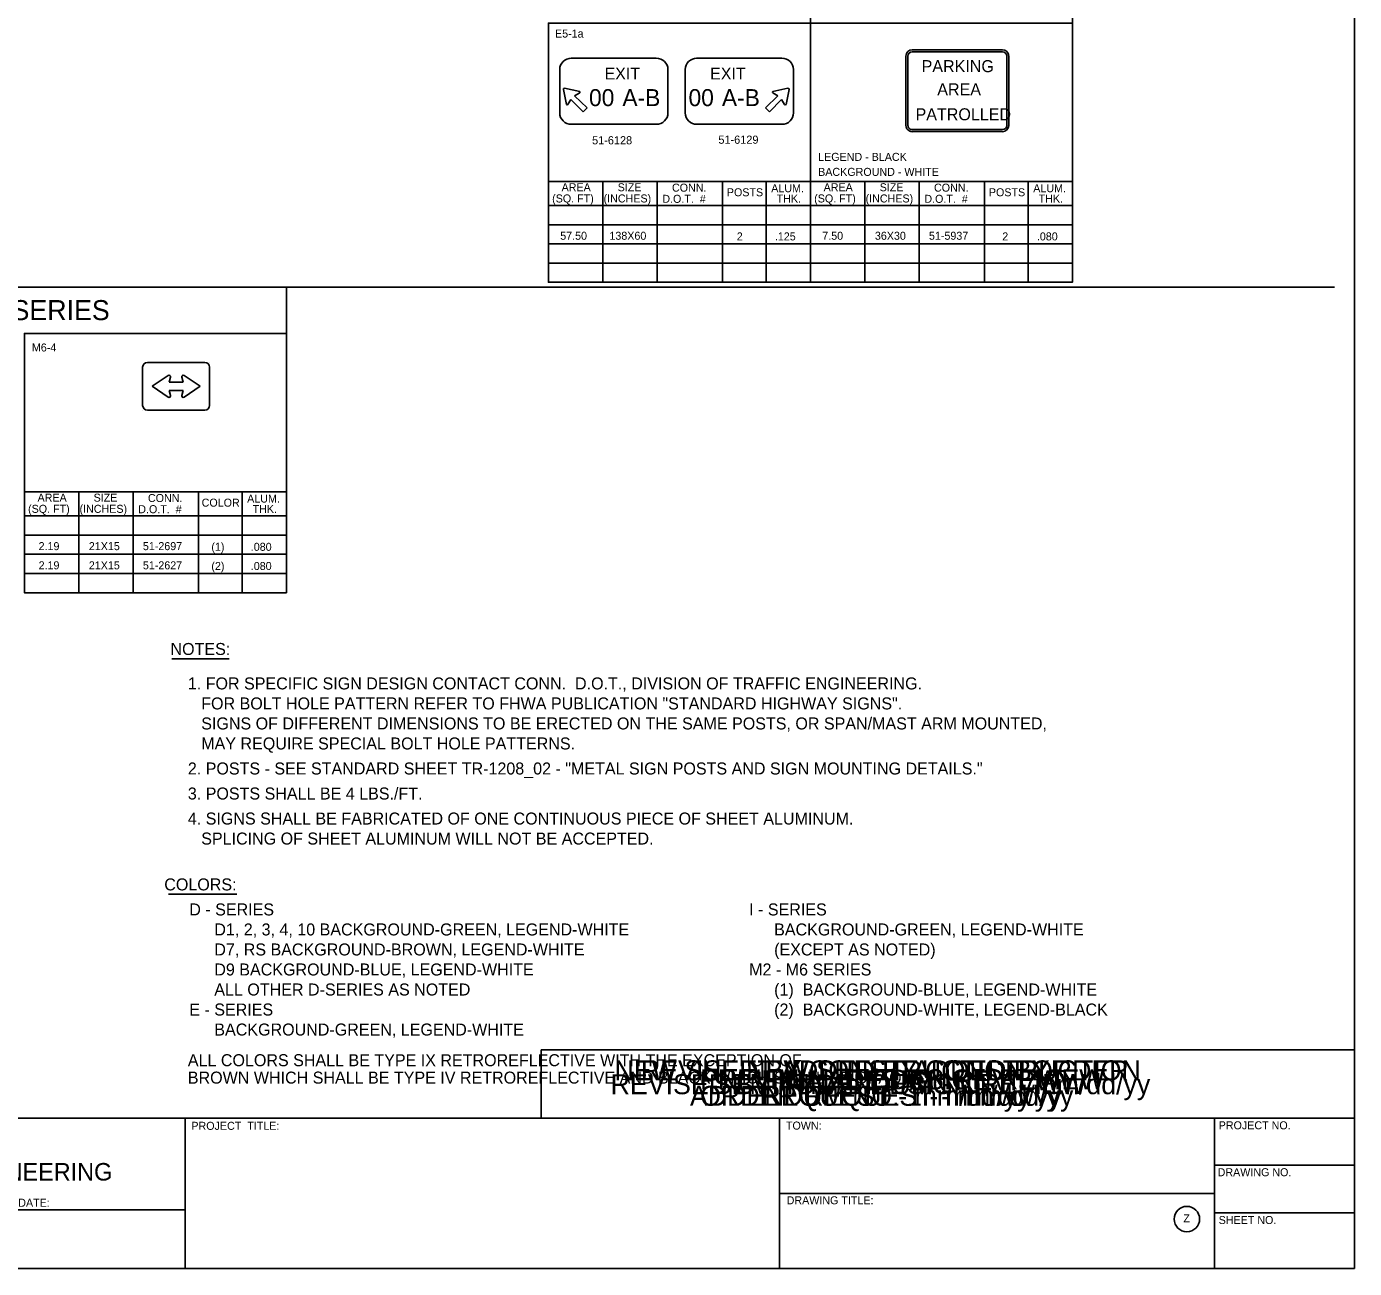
# Model space of a CAD drawing. Extents: x 0 to 2011, y -22 to 1183.
# Drawn here: x 739 to 1270, y -1 to 495 of the extents above; entities that cross this region are included whole.
import ezdxf

# ---------------------------------------------------------------- set-up
doc = ezdxf.new("R2010")
doc.units = 0
for name, color, linetype in [('CT_Bdr_Txt_Titleblock', 7, 'Continuous'), ('CT_Border_Perimeter_Shape', 7, 'Continuous'), ('CT_Construction', 7, 'Continuous'), ('CT_Note_Final_Design_Review', 7, 'Continuous'), ('CT_Note_New_Sheet_by_Addendum', 7, 'Continuous'), ('CT_Note_New_Sheet_by_Const_Order', 7, 'Continuous'), ('CT_Note_Preliminary_Design_Review', 7, 'Continuous'), ('CT_Note_Revised_Sheet_by_Addendum', 7, 'Continuous'), ('CT_Note_Revised_Sheet_by_Const_Order', 7, 'Continuous'), ('CT_Note_Semi_Final_Design_Review', 7, 'Continuous'), ('CT_Signature_Field_CTDOT', 7, 'Continuous'), ('CT_Title_Block_Linework', 7, 'Continuous'), ('CT_Title_Block_Text', 7, 'Continuous'), ('Default', 7, 'Continuous'), ('Level 1', 7, 'Continuous'), ('Level 2', 7, 'Continuous'), ('Level 5', 7, 'Continuous')]:
    doc.layers.add(name, color=color, linetype=linetype)

msp = doc.modelspace()

# ---------------------------------------------------------------- linework, layer by layer
at = {"layer": 'CT_Border_Perimeter_Shape'}
msp.add_lwpolyline([(0, -0.97), (1270, -0.97), (1270, 829.03), (0, 829.03)], close=True, dxfattribs=at)
at = {"layer": 'CT_Construction'}
msp.add_lwpolyline([(0, 829.03), (1270, 829.03), (1270, 59.03), (0, 59.03)], close=True, dxfattribs=at)
at = {"layer": 'CT_Note_Final_Design_Review'}
msp.add_lwpolyline([(944.83, 86.47), (1270, 86.47), (1270, 59.03), (944.83, 59.03)], close=True, dxfattribs=at)
at = {"layer": 'CT_Note_New_Sheet_by_Addendum'}
msp.add_lwpolyline([(944.83, 86.47), (1270, 86.47), (1270, 59.03), (944.83, 59.03)], close=True, dxfattribs=at)
msp.add_lwpolyline([(944.83, 86.47), (1270, 86.47), (1270, 59.03), (944.83, 59.03)], close=True, dxfattribs=at)
at = {"layer": 'CT_Note_New_Sheet_by_Const_Order'}
msp.add_lwpolyline([(944.83, 86.47), (1270, 86.47), (1270, 59.03), (944.83, 59.03)], close=True, dxfattribs=at)
msp.add_lwpolyline([(944.83, 86.47), (1270, 86.47), (1270, 59.03), (944.83, 59.03)], close=True, dxfattribs=at)
at = {"layer": 'CT_Note_Preliminary_Design_Review'}
msp.add_lwpolyline([(944.83, 86.47), (1270, 86.47), (1270, 59.03), (944.83, 59.03)], close=True, dxfattribs=at)
at = {"layer": 'CT_Note_Revised_Sheet_by_Addendum'}
msp.add_lwpolyline([(944.83, 86.47), (1270, 86.47), (1270, 59.03), (944.83, 59.03)], close=True, dxfattribs=at)
msp.add_lwpolyline([(944.83, 86.47), (1270, 86.47), (1270, 59.03), (944.83, 59.03)], close=True, dxfattribs=at)
at = {"layer": 'CT_Note_Revised_Sheet_by_Const_Order'}
msp.add_lwpolyline([(944.83, 86.47), (1270, 86.47), (1270, 59.03), (944.83, 59.03)], close=True, dxfattribs=at)
msp.add_lwpolyline([(944.83, 86.47), (1270, 86.47), (1270, 59.03), (944.83, 59.03)], close=True, dxfattribs=at)
at = {"layer": 'CT_Note_Semi_Final_Design_Review'}
msp.add_lwpolyline([(944.83, 86.47), (1270, 86.47), (1270, 59.03), (944.83, 59.03)], close=True, dxfattribs=at)
msp.add_lwpolyline([(944.83, 86.47), (1270, 86.47), (1270, 59.03), (944.83, 59.03)], close=True, dxfattribs=at)
at = {"layer": 'CT_Signature_Field_CTDOT'}
msp.add_line((651.86, 22.46), (802.52, 22.46), dxfattribs=at)
at = {"layer": 'CT_Title_Block_Linework'}
for p, q in [((1270, 59.03), (0, 59.03)), ((802.52, 59.03), (802.52, -0.97)), ((1040.16, 59.03), (1040.16, -0.97)), ((1214.02, 59.03), (1214.02, -0.97)), ((1214.02, 40.28), (1270, 40.28)), ((1040.16, 29.03), (1214.02, 29.03)), ((1214.02, 21.28), (1270, 21.28))]:
    msp.add_line(p, q, dxfattribs=at)
msp.add_circle((1203.02, 18.75), 5.08, dxfattribs=at)
at = {"layer": 'Default'}
msp.add_line((1262.03, 391.26), (5.05, 391.26), dxfattribs=at)
at = {"layer": 'Level 1'}
for p, q in [((1090.71, 455.87), (1090.71, 483.65)), ((1091.52, 455.87), (1091.52, 483.65)), ((1093.18, 486.11), (1129.32, 486.11)), ((1093.18, 485.31), (1129.32, 485.31)), ((1130.98, 483.65), (1130.98, 455.87)), ((1131.79, 483.65), (1131.79, 455.87)), ((952.3, 460.89), (952.3, 478.22)), ((956.86, 482.76), (986.55, 482.76)), ((956.86, 482.76), (990.9, 482.76)), ((995.57, 478.22), (995.57, 460.6)), ((1002.48, 460.89), (1002.48, 478.22)), ((1007.04, 482.76), (1036.73, 482.76)), ((1007.04, 482.76), (1041.09, 482.76)), ((1045.76, 478.22), (1045.76, 460.6)), ((953.76, 470.24), (954.97, 464.2)), ((960.29, 469.52), (954.25, 470.73)), ((958.25, 467.72), (960.29, 468.93)), ((963.21, 462.87), (958.25, 467.72)), ((1034.53, 462.87), (1039.49, 467.72)), ((1037.45, 469.52), (1043.49, 470.73)), ((1039.49, 467.72), (1037.45, 468.93)), ((1043.98, 470.24), (1042.77, 464.2)), ((955.56, 464.2), (956.77, 466.24)), ((956.77, 466.24), (961.62, 461.28)), ((961.62, 461.28), (963.21, 462.87)), ((1036.12, 461.28), (1034.53, 462.87)), ((1040.97, 466.24), (1036.12, 461.28)), ((1042.18, 464.2), (1040.97, 466.24)), ((990.9, 456.36), (956.97, 456.36)), ((1041.09, 456.36), (1007.15, 456.36)), ((1129.32, 454.21), (1093.18, 454.21)), ((1129.32, 453.41), (1093.18, 453.41)), ((810.43, 361.2), (787.48, 361.2)), ((810.43, 361.2), (787.48, 361.2)), ((785.57, 359.29), (785.57, 343.99)), ((785.57, 359.29), (785.57, 343.99)), ((795.73, 355.99), (789.39, 351.64)), ((808.52, 351.64), (802.18, 355.99)), ((812.34, 343.99), (812.34, 359.29)), ((812.34, 343.99), (812.34, 359.29)), ((789.39, 351.64), (789.39, 351.64)), ((789.39, 351.64), (795.73, 347.29)), ((796.11, 353.32), (796.7, 355.28)), ((801.8, 353.32), (796.11, 353.32)), ((801.21, 355.28), (801.8, 353.32)), ((802.18, 347.29), (808.52, 351.64)), ((808.52, 351.64), (808.52, 351.64)), ((808.52, 351.64), (808.52, 351.64)), ((796.7, 348), (796.11, 349.97)), ((796.11, 349.97), (801.8, 349.97)), ((801.8, 349.97), (801.21, 348)), ((787.48, 342.08), (810.43, 342.08)), ((787.48, 342.08), (810.43, 342.08)), ((797.3, 242.69), (820.15, 242.69)), ((795.89, 148.62), (823.17, 148.62))]:
    msp.add_line(p, q, dxfattribs=at)
for centre, radius, start, end in [((1093.18, 483.65), 2.47, 90, 180), ((1093.18, 483.65), 1.66, 90, 180), ((1129.32, 483.65), 2.47, 0.0023, 89.9991), ((1129.32, 483.65), 1.66, 0.0023, 89.9987), ((954.17, 470.32), 0.418, 78.7145, 191.291), ((959.99, 469.23), 0.418, 315, 45), ((1037.75, 469.23), 0.418, 135, 225), ((1043.57, 470.32), 0.418, 348.709, 101.2855), ((955.26, 464.5), 0.418, 225, 315), ((1042.47, 464.5), 0.418, 225, 315), ((1093.18, 455.87), 2.47, 179.998, 270), ((1089.87, 455.87), 0.84, 359.998, 0), ((1093.18, 455.87), 1.66, 179.998, 270), ((1089.87, 455.87), 1.64, 359.998, 0), ((1093.18, 452.57), 1.64, 90, 90.0015), ((1093.18, 452.57), 0.84, 90, 90.0015), ((1129.32, 455.87), 1.66, 270, 360), ((1129.32, 455.87), 2.47, 270, 360), ((787.48, 359.29), 1.91, 90, 180), ((787.48, 359.29), 1.91, 90, 180), ((810.43, 359.29), 1.91, 0, 90), ((810.43, 359.29), 1.91, 0, 90), ((796.09, 355.47), 0.637, 343.3591, 124.4886), ((801.82, 355.47), 0.637, 55.5114, 196.6409), ((796.09, 347.82), 0.637, 235.5114, 16.6409), ((801.82, 347.82), 0.637, 163.3591, 304.4886), ((787.48, 343.99), 1.91, 180, 270), ((787.48, 343.99), 1.91, 180, 270), ((810.43, 343.99), 1.91, 270, 360), ((810.43, 343.99), 1.91, 270, 360)]:
    msp.add_arc(centre, radius, start, end, dxfattribs=at)
for centre, major_axis, ratio, start_param, end_param in [((956.97, 478.22), (-4.67, 0), 0.970874, 4.712389, 6.283185), ((990.9, 478.22), (-4.67, 0), 0.97089, 3.141593, 4.712389), ((1007.15, 478.22), (-4.67, 0), 0.970874, 4.712389, 6.283185), ((1041.09, 478.22), (-4.67, 0), 0.97089, 3.141593, 4.712389), ((956.97, 460.89), (4.67, 0), 0.970874, 3.141593, 4.712389), ((990.9, 460.89), (4.67, 0), 0.970874, 4.712389, 6.283185), ((1007.15, 460.89), (4.67, 0), 0.970874, 3.141593, 4.712389), ((1041.09, 460.89), (4.67, 0), 0.970874, 4.712389, 6.283185)]:
    msp.add_ellipse(centre, major_axis=major_axis, ratio=ratio, start_param=start_param, end_param=end_param, dxfattribs=at)
at = {"layer": 'Level 2'}
for p, q in [((947.79, 433.47), (1052.53, 433.47)), ((969.54, 433.47), (969.54, 393.19)), ((991.29, 433.47), (991.29, 393.19)), ((1017.39, 433.47), (1017.39, 393.19)), ((1034.79, 433.47), (1034.79, 393.19)), ((1052.53, 433.47), (1157.28, 433.47)), ((1074.28, 433.47), (1074.28, 393.19)), ((1096.03, 433.47), (1096.03, 393.19)), ((1122.13, 433.47), (1122.13, 393.19)), ((1139.53, 433.47), (1139.53, 393.19)), ((947.79, 423.88), (1052.53, 423.88)), ((1052.53, 423.88), (1157.28, 423.88)), ((947.79, 416.2), (1052.53, 416.2)), ((1052.53, 416.2), (1157.28, 416.2)), ((947.79, 408.53), (1052.53, 408.53)), ((1052.53, 408.53), (1157.28, 408.53)), ((947.79, 400.86), (1052.53, 400.86)), ((1052.53, 400.86), (1157.28, 400.86)), ((812.34, 361.2), (812.34, 361.2)), ((785.57, 342.08), (785.57, 342.08)), ((738.29, 309.4), (843.04, 309.4)), ((760.04, 309.4), (760.04, 269.13)), ((781.79, 309.4), (781.79, 269.13)), ((807.89, 309.4), (807.89, 269.13)), ((825.29, 309.4), (825.29, 269.13)), ((738.29, 299.81), (843.04, 299.81)), ((738.29, 292.14), (843.04, 292.14)), ((738.29, 284.47), (843.04, 284.47)), ((738.29, 276.8), (843.04, 276.8))]:
    msp.add_line(p, q, dxfattribs=at)
for points in [[(1052.53, 496.81), (947.79, 496.81), (947.79, 393.19), (1052.53, 393.19)], [(1157.28, 496.81), (1052.53, 496.81), (1052.53, 393.19), (1157.28, 393.19)], [(843.04, 372.75), (738.29, 372.75), (738.29, 269.13), (843.04, 269.13)]]:
    msp.add_lwpolyline(points, close=True, dxfattribs=at)
msp.add_lwpolyline([(804.12, 354.65), (804.12, 354.66)], dxfattribs=at)
at = {"layer": 'Level 5'}
for p, q in [((1052.53, 830), (1052.53, 393.19)), ((1157.28, 830), (1157.28, 393.19)), ((843.04, 391.26), (843.04, 269.13))]:
    msp.add_line(p, q, dxfattribs=at)

# ---------------------------------------------------------------- texts
at = {"layer": 'CT_Bdr_Txt_Titleblock'}
msp.add_text('Z', height=3.2, dxfattribs=at).set_placement((1201.62, 17.47))
at = {"layer": 'CT_Note_Final_Design_Review'}
msp.add_text('FINAL DESIGN REVIEW', height=8, dxfattribs=at).set_placement((1032.99, 70.22))
at = {"layer": 'CT_Note_New_Sheet_by_Addendum'}
for s, p in [('NEW SHEET ADDED BY', (1026.89, 74.2)), ('ADDENDUM NO. 1 - mm/dd/yy', (1004.36, 64.04))]:
    msp.add_text(s, height=8, dxfattribs=at).set_placement(p)
at = {"layer": 'CT_Note_New_Sheet_by_Const_Order'}
for s, p in [('NEW SHEET ADDED BY CONSTRUCTION', (974.21, 74.2)), ('ORDER REQUEST - mm/dd/yy', (1008.44, 64.04))]:
    msp.add_text(s, height=8, dxfattribs=at).set_placement(p)
at = {"layer": 'CT_Note_Preliminary_Design_Review'}
msp.add_text('PRELIMINARY DESIGN REVIEW', height=8, rotation=360, dxfattribs=at).set_placement((1008.39, 70.59))
at = {"layer": 'CT_Note_Revised_Sheet_by_Addendum'}
msp.add_text('REVISED BY ADDENDUM NO. 1 - mm/dd/yy', height=8, dxfattribs=at).set_placement((972.63, 68.66))
at = {"layer": 'CT_Note_Revised_Sheet_by_Const_Order'}
for s, p in [('REVISED BY CONSTRUCTION ORDER', (984.74, 74.19)), ('REQUEST - mm/dd/yy', (1032.95, 64.03))]:
    msp.add_text(s, height=8, dxfattribs=at).set_placement(p)
at = {"layer": 'CT_Note_Semi_Final_Design_Review'}
msp.add_text('SEMI FINAL DESIGN REVIEW', height=8, dxfattribs=at).set_placement((1013.84, 68.77))
at = {"layer": 'CT_Signature_Field_CTDOT'}
for s, height, p in [('OFFICE OF ENGINEERING', 7, (655.38, 34.16)), ('DATE:  ', 3.2, (735.85, 23.69))]:
    msp.add_text(s, height=height, rotation=360, dxfattribs=at).set_placement(p)
at = {"layer": 'CT_Title_Block_Text'}
for s, p in [('PROJECT  TITLE:', (805.05, 54.43)), ('TOWN:', (1042.74, 54.53)), ('PROJECT NO.', (1215.74, 54.64)), ('DRAWING NO.', (1215.31, 35.88)), ('DRAWING TITLE:', (1043.02, 24.66)), ('SHEET NO.', (1215.72, 16.78))]:
    msp.add_text(s, height=3.2, rotation=360, dxfattribs=at).set_placement(p)
at = {"layer": 'Level 1'}
for s, height, p in [('51-6128', 3.264, (965.24, 448.33)), ('51-6129', 3.264, (1015.73, 448.57)), ('M6 - SERIES', 8, (708.8, 378.08)), ('NOTES:', 4.8, (796.71, 244.23)), ('1. FOR SPECIFIC SIGN DESIGN CONTACT CONN.  D.O.T., DIVISION OF TRAFFIC ENGINEERING.', 4.8, (803.64, 230.46)), ('   FOR BOLT HOLE PATTERN REFER TO FHWA PUBLICATION "STANDARD HIGHWAY SIGNS".', 4.8, (803.64, 222.46)), ('   SIGNS OF DIFFERENT DIMENSIONS TO BE ERECTED ON THE SAME POSTS, OR SPAN/MAST ARM MOUNTED,', 4.8, (803.64, 214.46)), ('   MAY REQUIRE SPECIAL BOLT HOLE PATTERNS.', 4.8, (803.64, 206.46)), ('2. POSTS - SEE STANDARD SHEET TR-1208_02 - "METAL SIGN POSTS AND SIGN MOUNTING DETAILS."', 4.8, (803.64, 196.46)), ('3. POSTS SHALL BE 4 LBS./FT.', 4.8, (803.64, 186.46)), ('4. SIGNS SHALL BE FABRICATED OF ONE CONTINUOUS PIECE OF SHEET ALUMINUM.', 4.8, (803.64, 176.46)), ('   SPLICING OF SHEET ALUMINUM WILL NOT BE ACCEPTED.', 4.8, (803.64, 168.46)), ('COLORS:', 4.8, (794.22, 150.12)), ('D - SERIES', 4.8, (804.22, 140.12)), ('I - SERIES', 4.8, (1028.02, 140.12)), ('D1, 2, 3, 4, 10 BACKGROUND-GREEN, LEGEND-WHITE', 4.8, (814.22, 132.12)), ('BACKGROUND-GREEN, LEGEND-WHITE', 4.8, (1038.02, 132.12)), ('D7, RS BACKGROUND-BROWN, LEGEND-WHITE', 4.8, (814.22, 124.12)), ('(EXCEPT AS NOTED)', 4.8, (1038.02, 124.12)), ('D9 BACKGROUND-BLUE, LEGEND-WHITE', 4.8, (814.22, 116.12)), ('M2 - M6 SERIES', 4.8, (1028.02, 116.12)), ('ALL OTHER D-SERIES AS NOTED', 4.8, (814.22, 108.12)), ('(1)  BACKGROUND-BLUE, LEGEND-WHITE', 4.8, (1038.02, 108.12)), ('E - SERIES', 4.8, (804.22, 100.12)), ('(2)  BACKGROUND-WHITE, LEGEND-BLACK', 4.8, (1038.02, 100.12)), ('BACKGROUND-GREEN, LEGEND-WHITE', 4.8, (814.22, 92.12)), ('ALL COLORS SHALL BE TYPE IX RETROREFLECTIVE WITH THE EXCEPTION OF ', 4.8, (803.64, 79.86)), ('BROWN WHICH SHALL BE TYPE IV RETROREFLECTIVE AND BLACK WHICH SHALL BE OPAQUE.', 4.8, (803.64, 72.9))]:
    msp.add_text(s, height=height, dxfattribs=at).set_placement(p)
at = {"layer": 'Level 2'}
for s, height, p in [('E5-1a', 3.2, (950.42, 491.02)), ('EXIT', 4.763, (970.23, 474.26)), ('EXIT', 4.763, (1012.45, 474.26)), ('PARKING', 4.8, (1096.98, 477.19)), ('AREA', 4.8, (1103.23, 467.93)), ('00', 6.804, (964.02, 463.61)), ('A-B', 6.804, (977.36, 463.61)), ('00', 6.804, (1003.8, 463.61)), ('A-B', 6.804, (1017.14, 463.61)), ('PATROLLED', 4.8, (1094.55, 457.95)), ('LEGEND - BLACK', 3.2, (1055.61, 441.73)), ('BACKGROUND - WHITE', 3.2, (1055.61, 435.73)), ('AREA', 3.2, (953.05, 429.58)), ('SIZE', 3.2, (975.47, 429.58)), ('CONN.', 3.2, (997.18, 429.43)), ('POSTS', 3.2, (1019.11, 427.58)), ('ALUM.', 3.2, (1036.85, 429.2)), ('AREA', 3.2, (1057.8, 429.58)), ('SIZE', 3.2, (1080.21, 429.58)), ('CONN.', 3.2, (1101.93, 429.43)), ('POSTS', 3.2, (1123.86, 427.58)), ('ALUM.', 3.2, (1141.6, 429.2)), ('(SQ. FT)', 3.2, (949.27, 425.11)), ('(INCHES)', 3.2, (969.84, 425.11)), ('D.O.T.  #', 3.2, (993.32, 424.96)), ('THK.', 3.2, (1039.03, 425.06)), ('(SQ. FT)', 3.2, (1054.02, 425.11)), ('(INCHES)', 3.2, (1074.58, 425.11)), ('D.O.T.  #', 3.2, (1098.07, 424.96)), ('THK.', 3.2, (1143.77, 425.06)), ('M6-4', 3.2, (741.3, 365.54)), ('AREA', 3.2, (743.56, 305.52)), ('SIZE', 3.2, (765.97, 305.52)), ('CONN.', 3.2, (787.69, 305.37)), ('ALUM.', 3.2, (827.35, 305.14)), ('(SQ. FT)', 3.2, (739.77, 301.05)), ('(INCHES)', 3.2, (760.34, 301.05)), ('D.O.T.  #', 3.2, (783.82, 300.9)), ('COLOR', 3.2, (809.16, 303.52)), ('THK.', 3.2, (829.53, 301))]:
    msp.add_text(s, height=height, dxfattribs=at).set_placement(p)
at = {"layer": 'Level 5'}
for s, p in [('57.50', (952.5, 410.2)), ('138X60', (972.17, 410.2)), ('2 ', (1023.08, 409.94)), ('.125', (1038.31, 409.94)), ('7.50 ', (1057.26, 410.2)), ('36X30', (1078.3, 410.2)), ('51-5937', (1099.91, 410.2)), ('2', (1129.21, 409.94)), ('.080', (1143.05, 409.94)), (' 2.19', (742.79, 286.14)), ('21X15', (764.06, 286.14)), ('51-2697', (785.66, 286.14)), ('(1)', (813.05, 285.87)), ('.080', (828.81, 285.87)), (' 2.19', (742.79, 278.47)), ('21X15', (764.06, 278.47)), ('51-2627', (785.66, 278.47)), ('(2)', (813.05, 278.2)), ('.080', (828.81, 278.2))]:
    msp.add_text(s, height=3.2, dxfattribs=at).set_placement(p)

doc.saveas('drawing.dxf')
